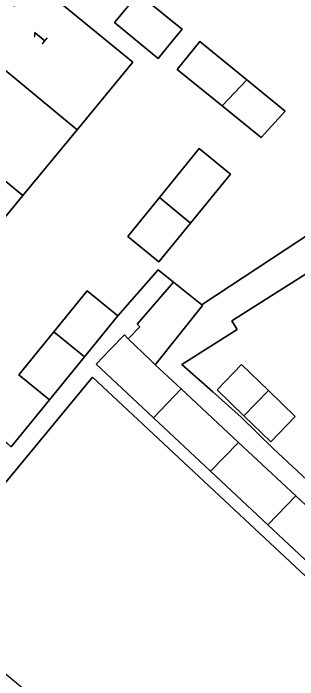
# Model space of a CAD drawing. Extents: x 162073 to 163043, y 381818 to 382561.
# Drawn here: x 162488.75 to 162508.83, y 382247.25 to 382294.33 of the extents above; entities that cross this region are included whole.
import ezdxf

# ---------------------------------------------------------------- set-up
doc = ezdxf.new("R2010")
doc.units = 0
for name, color, linetype in [('IMGEO_Erf', 7, 'Continuous'), ('IMGEO_Pand', 7, 'Continuous'), ('IMGEO_Pand_nummerreeks', 7, 'Continuous'), ('IMGEO_Voetpad_open', 7, 'Continuous')]:
    doc.layers.add(name, color=color, linetype=linetype)

msp = doc.modelspace()

# ---------------------------------------------------------------- linework, layer by layer
at = {"layer": 'IMGEO_Erf'}
for points in [[(162490.252, 382296.582), (162494.111, 382293.403), (162497.184, 382290.872), (162493.259, 382286.105), (162489.431, 382281.457), (162485.595, 382276.798)], [(162457.619, 382263.189), (162459.18, 382261.904), (162475.761, 382248.251), (162478.317, 382251.355), (162474.824, 382254.232), (162476.565, 382256.346), (162480.058, 382253.468), (162483.451, 382257.921), (162481.553, 382259.466), (162483.988, 382262.459), (162486.44, 382265.471), (162488.329, 382263.933), (162488.605, 382263.708), (162491.308, 382267.028), (162489.142, 382268.791), (162491.617, 382271.833), (162493.971, 382274.724), (162496.137, 382272.961), (162498.99, 382276.207), (162500.055, 382275.334), (162502.069, 382273.725), (162502.096, 382273.753), (162518.927, 382284.853)], [(162521.381, 382283.497), (162504.175, 382272.599), (162504.564, 382271.986), (162500.644, 382269.516), (162502.833, 382267.581), (162504.845, 382265.802), (162507.097, 382263.591), (162511.538, 382259.449)], [(162546.943, 382219.45), (162494.331, 382268.629), (162482.206, 382253.929), (162481.569, 382253.156), (162483.282, 382251.74), (162483.952, 382251.186), (162485.979, 382249.511), (162488.441, 382247.475), (162490.227, 382246)]]:
    msp.add_lwpolyline(points, dxfattribs=at)
for points in [[(162495.898, 382293.681), (162497.592, 382295.738), (162500, 382293.755), (162500.672, 382293.201), (162500, 382292.385), (162498.978, 382291.144)], [(162500.323, 382290.369), (162501.916, 382292.327), (162505.247, 382289.617), (162507.945, 382287.422), (162506.245, 382285.552), (162503.49, 382287.793)], [(162499.069, 382281.315), (162501.88, 382284.769), (162504.086, 382282.974), (162501.264, 382279.505), (162499.035, 382276.765), (162496.828, 382278.561)], [(162506.927, 382264.063), (162505.036, 382265.902), (162503.144, 382267.74), (162504.872, 382269.518), (162506.764, 382267.679), (162508.655, 382265.84)]]:
    msp.add_lwpolyline(points, close=True, dxfattribs=at)
at = {"layer": 'IMGEO_Pand'}
for points in [[(162493.259, 382286.105), (162497.184, 382290.872), (162494.111, 382293.403), (162490.252, 382296.582), (162488.816, 382294.839), (162488.311, 382295.255), (162486.387, 382292.919), (162486.927, 382292.474), (162486.363, 382291.79)], [(162498.978, 382291.144), (162500, 382292.385), (162500.672, 382293.201), (162500, 382293.755), (162497.592, 382295.738), (162495.898, 382293.681)], [(162505.247, 382289.617), (162501.916, 382292.327), (162500.323, 382290.369), (162503.49, 382287.793)], [(162493.259, 382286.105), (162486.363, 382291.79), (162485.041, 382290.185), (162484.488, 382290.64), (162482.557, 382288.295), (162483.104, 382287.845), (162482.523, 382287.139), (162489.431, 382281.457)], [(162505.247, 382289.617), (162503.49, 382287.793), (162506.245, 382285.552), (162507.945, 382287.422)], [(162478.655, 382282.52), (162485.595, 382276.798), (162489.431, 382281.457), (162482.523, 382287.139), (162481.206, 382285.541), (162480.659, 382285.992), (162478.762, 382283.688), (162479.271, 382283.269)], [(162501.264, 382279.505), (162504.086, 382282.974), (162501.88, 382284.769), (162499.069, 382281.315)], [(162501.264, 382279.505), (162499.069, 382281.315), (162496.828, 382278.561), (162499.035, 382276.765)], [(162502.069, 382273.725), (162500.055, 382275.334), (162497.488, 382272.374), (162497.684, 382272.183), (162496.866, 382271.343), (162498.431, 382269.83), (162498.612, 382269.654), (162498.771, 382269.506), (162502.114, 382273.689)], [(162496.137, 382272.961), (162493.971, 382274.724), (162491.617, 382271.833), (162493.772, 382270.056)], [(162493.772, 382270.056), (162491.617, 382271.833), (162489.142, 382268.791), (162491.308, 382267.028)], [(162498.771, 382269.506), (162498.612, 382269.654), (162498.431, 382269.83), (162496.866, 382271.343), (162496.593, 382271.607), (162495.595, 382270.576), (162494.597, 382269.544), (162498.641, 382265.76), (162500.606, 382267.791)], [(162506.764, 382267.679), (162504.872, 382269.518), (162503.144, 382267.74), (162505.036, 382265.902)], [(162504.652, 382264.011), (162500.606, 382267.791), (162498.641, 382265.76), (162502.685, 382261.976)], [(162506.764, 382267.679), (162505.036, 382265.902), (162506.927, 382264.063), (162508.655, 382265.84)], [(162508.699, 382260.23), (162504.652, 382264.011), (162502.685, 382261.976), (162506.728, 382258.193)], [(162508.699, 382260.23), (162506.728, 382258.193), (162510.772, 382254.409), (162512.745, 382256.45)]]:
    msp.add_lwpolyline(points, close=True, dxfattribs=at)
at = {"layer": 'IMGEO_Voetpad_open'}
for points in [[(162518.927, 382284.853), (162502.096, 382273.753), (162502.069, 382273.725), (162502.114, 382273.689), (162498.771, 382269.506), (162500.606, 382267.791), (162504.652, 382264.011), (162508.699, 382260.23), (162512.745, 382256.45)], [(162511.538, 382259.449), (162507.097, 382263.591), (162504.845, 382265.802), (162502.833, 382267.581), (162500.644, 382269.516), (162504.564, 382271.986), (162504.175, 382272.599), (162521.381, 382283.497)], [(162510.772, 382254.409), (162506.728, 382258.193), (162502.685, 382261.976), (162498.641, 382265.76), (162494.597, 382269.544), (162495.595, 382270.576), (162496.593, 382271.607), (162496.866, 382271.343), (162497.684, 382272.183), (162497.488, 382272.374), (162500.055, 382275.334), (162498.99, 382276.207), (162496.137, 382272.961), (162493.772, 382270.056), (162491.308, 382267.028), (162488.605, 382263.708)], [(162482.206, 382253.929), (162494.331, 382268.629), (162546.943, 382219.45)]]:
    msp.add_lwpolyline(points, dxfattribs=at)

# ---------------------------------------------------------------- texts
at = {"layer": 'IMGEO_Pand_nummerreeks'}
msp.add_text('1', height=1, rotation=50.4938, dxfattribs=at).set_placement((162490.763, 382292.045))

doc.saveas('drawing.dxf')
